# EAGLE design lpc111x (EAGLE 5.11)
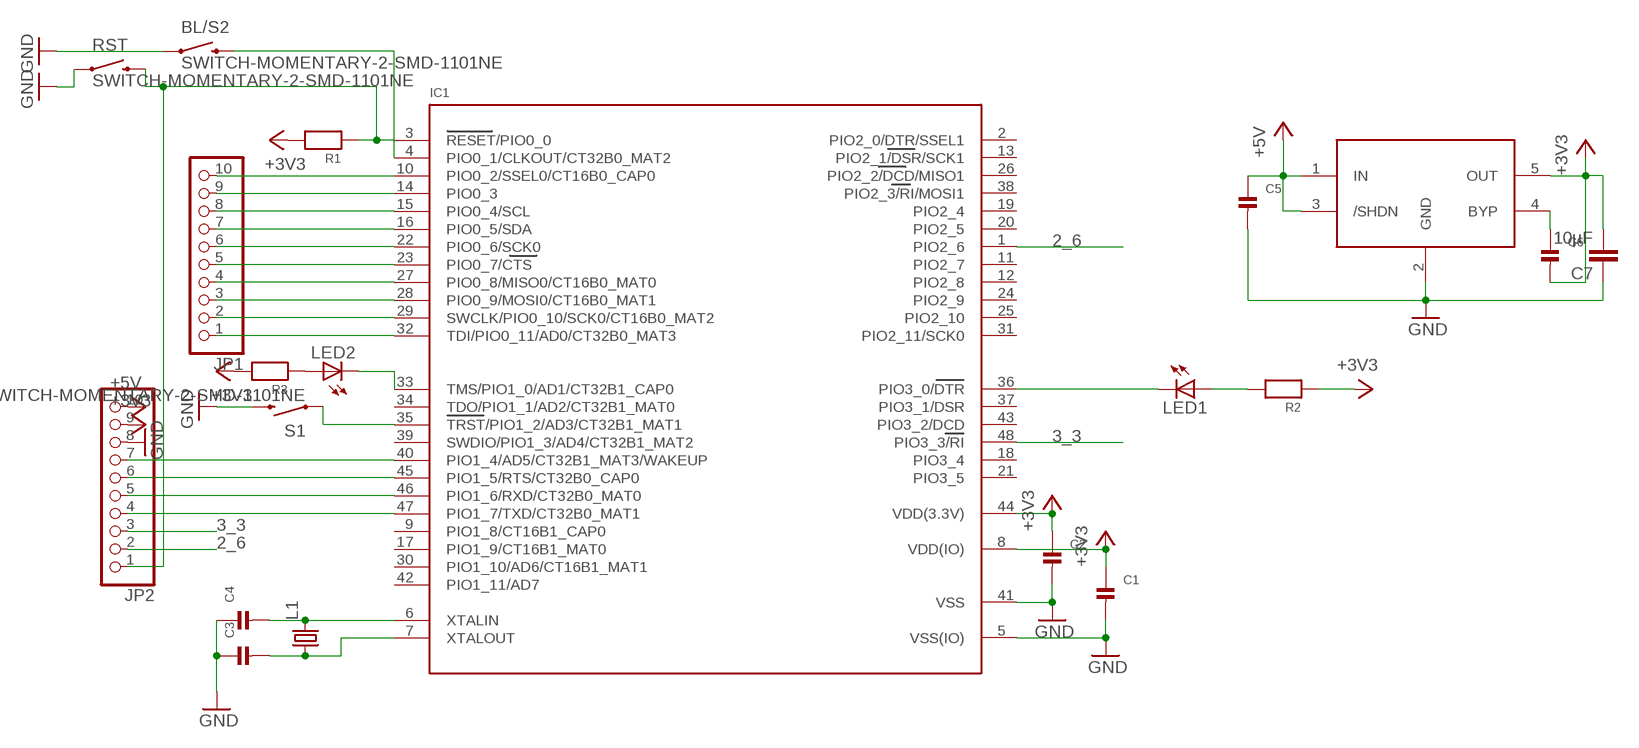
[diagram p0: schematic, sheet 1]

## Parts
BL/S2  SWITCH-MOMENTARY-2-SMD-1101NE  [TACTILE-SWITCH-1101NE]
C1  CAP_CERAMIC0603MINI  [0603-MINI]
C2  CAP_CERAMIC0603MINI  [0603-MINI]
C3  CAP_CERAMIC0603MINI  [0603-MINI]
C4  CAP_CERAMIC0603MINI  [0603-MINI]
C5  CAP_CERAMIC0603MINI  [0603-MINI]
C6  CAP_CERAMIC0603MINI  [0603-MINI]
C7  10µF  CAP0805  [0805]
IC1  LPC1113/4  [LQFP48]
IC2  LT1761  [SOT23-5L]
JP1  PINHD-1X10_2.54  [1X10]
JP2  PINHD-1X10_2.54  [1X10]
L1  X22-OSCILLATOR  [X22]
LED1  LEDCHIPLED_0805  [CHIPLED_0805]
LED2  LEDCHIPLED_0805  [CHIPLED_0805]
R1  RESISTOR0402  [0402]
R2  RESISTOR0402  [0402]
R3  RESISTOR0402  [0402]
RST  SWITCH-MOMENTARY-2-SMD-1101NE  [TACTILE-SWITCH-1101NE]
S1  SWITCH-MOMENTARY-2-SMD-1101NE  [TACTILE-SWITCH-1101NE]

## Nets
2_6: IC1.1(PIO2_6) JP2.2
3_3: IC1.48(PIO3_3/RI) JP2.3
+3V3: C1.1 C2.1 C6.2 C7.2 IC1.8(VDD(IO)) IC1.44(VDD(3.3V)) IC2.5(OUT) JP2.9 R1.2 R2.1 R3.2
+5V: C5.1 IC2.1(IN) IC2.3(/SHDN) JP2.10
GND: BL/S2.P$1 C1.2 C2.2 C3.1 C4.1 C5.2 C7.1 IC1.5(VSS(IO)) IC1.41(VSS) IC2.2(GND) JP2.8 RST.P$1 S1.P$2
N$1: IC1.32(TDI/PIO0_11/AD0/CT32B0_MAT3) JP1.1
N$2: IC1.29(SWCLK/PIO0_10/SCK0/CT16B0_MAT2) JP1.2
N$3: C3.2 IC1.7(XTALOUT) L1.1
N$4: C4.2 IC1.6(XTALIN) L1.3
N$5: IC1.28(PIO0_9/MOSI0/CT16B0_MAT1) JP1.3
N$6: IC1.27(PIO0_8/MISO0/CT16B0_MAT0) JP1.4
N$7: IC1.3(RESET/PIO0_0) JP2.1 R1.1 RST.P$2
N$8: IC1.23(PIO0_7/CTS) JP1.5
N$9: IC1.22(PIO0_6/SCK0) JP1.6
N$12: IC1.14(PIO0_3) JP1.9
N$13: IC1.10(PIO0_2/SSEL0/CT16B0_CAP0) JP1.10
N$16: IC1.45(PIO1_5/RTS/CT32B0_CAP0) JP2.6
N$17: IC1.40(PIO1_4/AD5/CT32B1_MAT3/WAKEUP) JP2.7
N$18: LED1.A R2.2
N$19: IC1.36(PIO3_0/DTR) LED1.C
N$20: IC1.35(TRST/PIO1_2/AD3/CT32B1_MAT1) S1.P$1
N$21: BL/S2.P$2 IC1.4(PIO0_1/CLKOUT/CT32B0_MAT2)
N$22: LED2.A R3.1
N$23: IC1.33(TMS/PIO1_0/AD1/CT32B1_CAP0) LED2.C
N$43: C6.1 IC2.4(BYP)
RX: IC1.46(PIO1_6/RXD/CT32B0_MAT0) JP2.5
SCL: IC1.15(PIO0_4/SCL) JP1.8
SDA: IC1.16(PIO0_5/SDA) JP1.7
TX: IC1.47(PIO1_7/TXD/CT32B0_MAT1) JP2.4
Unconnected: IC1.2(PIO2_0/DTR/SSEL1) IC1.9(PIO1_8/CT16B1_CAP0) IC1.11(PIO2_7) IC1.12(PIO2_8) IC1.13(PIO2_1/DSR/SCK1) IC1.17(PIO1_9/CT16B1_MAT0) IC1.18(PIO3_4) IC1.19(PIO2_4) IC1.20(PIO2_5) IC1.21(PIO3_5) IC1.24(PIO2_9) IC1.25(PIO2_10) IC1.26(PIO2_2/DCD/MISO1) IC1.30(PIO1_10/AD6/CT16B1_MAT1) IC1.31(PIO2_11/SCK0) IC1.34(TDO/PIO1_1/AD2/CT32B1_MAT0) IC1.37(PIO3_1/DSR) IC1.38(PIO2_3/RI/MOSI1) IC1.39(SWDIO/PIO1_3/AD4/CT32B1_MAT2) IC1.42(PIO1_11/AD7) IC1.43(PIO3_2/DCD)

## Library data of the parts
BL/S2 RST S1 = SparkFun:SWITCH-MOMENTARY-2
C1-C6 = microbuilder:CAP_CERAMIC: Ceramic Capacitors
C7 = SparkFun:CAP: Capacitor
IC1 = microbuilder:LPC1113/4: LPC1113/4 MCU QFP48 Package ARM Cortex M0, 50MHz Operation, 8 Channel 10-Bit ADC, 1²C, 2xSPI, UART, 2x16 Bit and 2x32 Bit Timers, Internal 12MHz Oscillator, 1.8-3.6V operation. Model Flash SRAM Part N°: Digikey Mouser LPC1113 24KB 8KB LPC1113FBD48/301 TBD TBD LPC1114 32KB 8KB LPC1114FBD48/301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; DIGIKEY#: 568-4950-ND; MANF: NXP; MANF#: LPC1114FBD48/301,1
IC2 = seb:LT1761
JP1 JP2 = pinhead-2:PINHD-1X10: PIN HEADER
L1 = seb:X22-OSCILLATOR
LED1 LED2 = led:LED: LED
R1-R3 = microbuilder:RESISTOR: Resistors

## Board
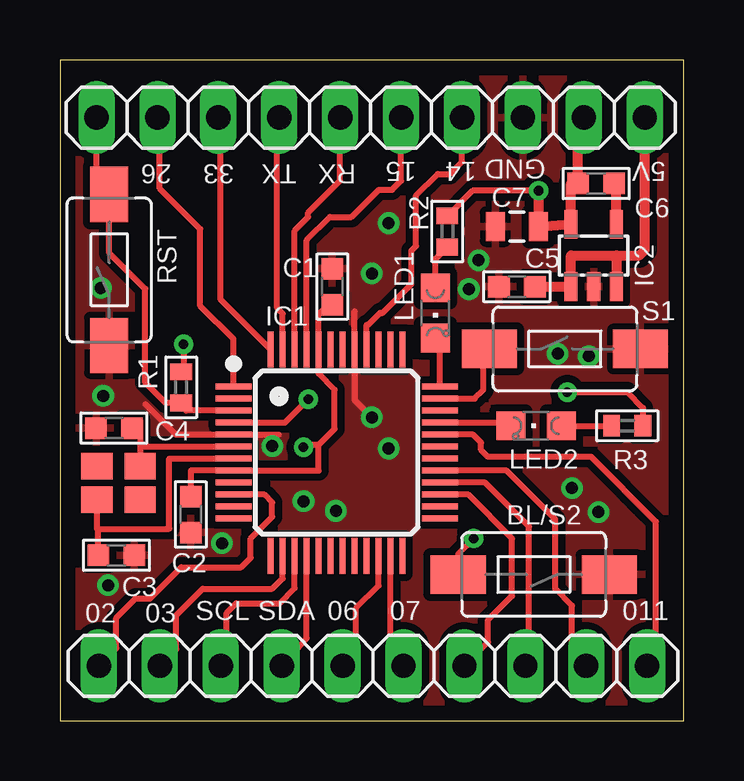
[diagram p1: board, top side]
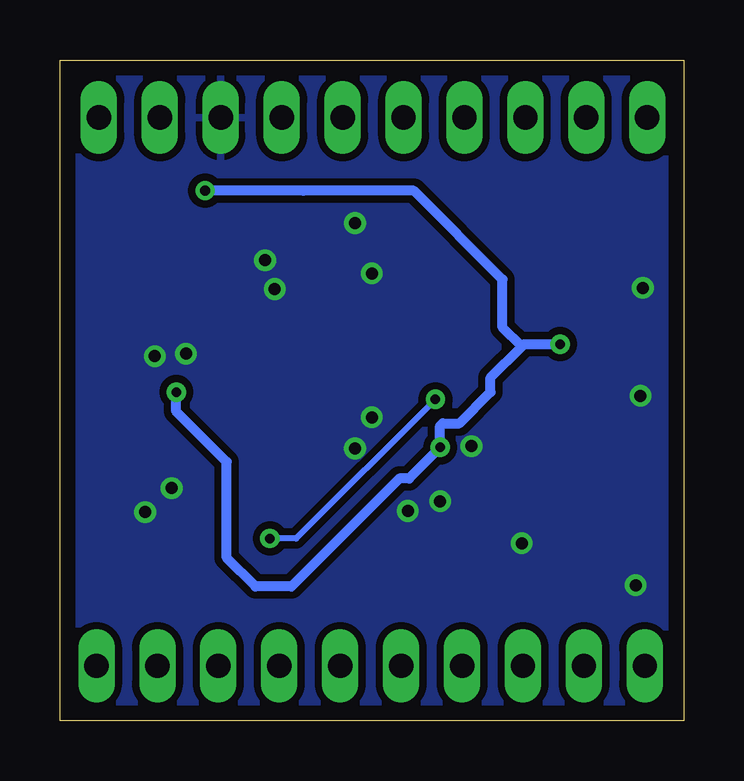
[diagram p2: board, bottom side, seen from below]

Size 26 x 27.55 mm. Coordinates in mm from the lower left corner, seen from the top.
Outline: 0,0 26,0 26,27.55 0,27.55 0,0
Copper layers (1*16): Top 0.035mm / dielectric 1.5mm / Bottom 0.035mm
Design rules "default *": minimum track width 10mil, minimum drill 24mil, track to track 8mil, track to pad 8mil, pad to pad 8mil, via to via 8mil, smd to smd 8mil, copper to edge 25mil, drill to drill 8mil, minimum pad ring 10mil, minimum via ring 8mil, stop-mask expansion 4mil, vias tented up to drill 40mil, thermal gap 10mil

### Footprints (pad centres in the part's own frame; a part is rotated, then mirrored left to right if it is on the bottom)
TACTILE-SWITCH-1101NE = smd 2.3 x 1.6: P$1 -3.15,0; P$2 3.15,0
0603-MINI = smd 0.9 x 0.9: 1 -0.75,0; 2 0.75,0
0805 = smd 0.8 x 1.2: 1 -0.9,0; 2 0.9,0
LQFP48 = smd 1.5 x 0.25: 1 -4.3,2.75; 2 -4.3,2.25; 3 -4.3,1.75; 4 -4.3,1.25; 5 -4.3,0.75; 6 -4.3,0.25; 7 -4.3,-0.25; 8 -4.3,-0.75; 9 -4.3,-1.25; 10 -4.3,-1.75; 11 -4.3,-2.25; 12 -4.3,-2.75; 25 4.3,-2.75; 26 4.3,-2.25; 27 4.3,-1.75; 28 4.3,-1.25; 29 4.3,-0.75; 30 4.3,-0.25; 31 4.3,0.25; 32 4.3,0.75; 33 4.3,1.25; 34 4.3,1.75; 35 4.3,2.25; 36 4.3,2.75 | smd 0.25 x 1.5: 13 -2.75,-4.3; 14 -2.25,-4.3; 15 -1.75,-4.3; 16 -1.25,-4.3; 17 -0.75,-4.3; 18 -0.25,-4.3; 19 0.25,-4.3; 20 0.75,-4.3; 21 1.25,-4.3; 22 1.75,-4.3; 23 2.25,-4.3; 24 2.75,-4.3; 37 2.75,4.3; 38 2.25,4.3; 39 1.75,4.3; 40 1.25,4.3; 41 0.75,4.3; 42 0.25,4.3; 43 -0.25,4.3; 44 -0.75,4.3; 45 -1.25,4.3; 46 -1.75,4.3; 47 -2.25,4.3; 48 -2.75,4.3
SOT23-5L = smd 0.55 x 1.2: 1 -0.95,-1.3; 2 0,-1.3; 3 0.95,-1.3; 4 0.95,1.3; 5 -0.95,1.3
1X10 = drill 1.016 long: 1 -11.43,0; 2 -8.89,0; 3 -6.35,0; 4 -3.81,0; 5 -1.27,0; 6 1.27,0; 7 3.81,0; 8 6.35,0; 9 8.89,0; 10 11.43,0
X22 = smd 1.3 x 1.1: 1 0.9,0.7; 2 -0.9,0.7; 3 -0.9,-0.7; 4 0.9,-0.7
CHIPLED_0805 = smd 1.2 x 1.2: A 0,-1.05; C 0,1.05
0402 = smd 0.7 x 0.9: 1 -0.65,0; 2 0.65,0

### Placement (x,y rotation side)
BL/S2  19.75,6.1 180 top
C1  11.35,18.1 90 top
C2  5.45,8.6 270 top
C3  2.35,6.9 180 top
C4  2.25,12.2 0 top
C5  19.05,18.1 180 top
C6  22.35,22.4 180 top
C7  19.05,20.6 0 top
IC1  11.53,11.18 0 top
IC2  22.25,19.4 0 top
JP1  13.05,2.29 180 top
JP2  12.95,25.15 0 top
L1  2.44,9.91 180 top
LED1  15.65,17 180 top
LED2  19.85,12.3 90 top
R1  5.05,13.9 90 top
R2  16.15,20.4 270 top
R3  23.65,12.3 0 top
RST  2.05,18.8 90 top
S1  21.05,15.5 0 top

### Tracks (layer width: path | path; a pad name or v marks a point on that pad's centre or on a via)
2_6
  Top 0.254: IC1.1 7.23,15.92 5.85,17.3 5.85,20.5 4.16,22.19 4.16,25.05 JP2.2
3_3
  Top 0.254: IC1.48 6.7,17.56 6.7,25.05 JP2.3
+3V3  (via drill 0.4)
  Top 0.254: C2.1 5.45,10.43 IC1.8 10.78,10.43 10.78,11.5 | C1.1 11.2,17.35 10.78,16.93 IC1.44 10.78,14.47 11.45,13.8 11.45,12.17 10.78,11.5 | v10.15,11.4 10.25,11.5 10.78,11.5 | R1.2 5.15,14.55 v5.15,15.7 | R2.1 17.2,22.1 v19.95,22.1 | R3.2 24.3,13.05 23.65,13.7 v21.15,13.7
  Top 0.406: v19.95,22.1 C7.2 IC2.5 21.3,22.4 C6.2 21.6,24.91 JP2.9
  Bottom 0.406: v19.95,22.1 15.85,22.1 11.25,22.1 7.55,18.4 7.55,16.4 6.75,15.6 | 6.75,15.6 8.05,14.3 8.05,13.7 9.35,12.4 10.05,12.4 10.15,12.3 v10.15,11.4 11.45,10.1 11.85,10.1 16.35,5.6 17.85,5.6 19.05,6.8 19.05,10.8 21.15,12.9 v21.15,13.7 | 6.75,15.6 6.65,15.7 v5.15,15.7
+5V
  Top 0.406: C5.1 IC2.1 21.3,19.4 23.2,19.4 | 23.2,19.4 IC2.3 | JP2.10 24.38,19.63 24.15,19.4 23.2,19.4
GND  (via drill 0.5)
  Top 0.254: IC1.41 12.28,14.97 | 12.28,14.97 12.28,13.37 v13,12.65 | 3.55,13.2 4.82,11.93 IC1.5 9.13,11.93 | 12.28,14.97 12.28,17.08
  other vias: 10.15,9.15 2,5.65 6.75,7.4 22.45,8.7 21.35,9.7 22.05,15.2 20.75,15.3 17.45,19.2 17.05,18 1.7,18.05 1.8,13.55 13,18.65 13.7,20.75 8.85,11.45 13.7,11.35 11.5,8.75
  pour Top (isolate 0.305): 0,0.4 26,0.4 26,27.15 0,27.15
  pour Bottom (isolate 0.305): 0,0.4 26,0.4 26,27.15 0,27.15
N$1
  Top 0.254: JP1.1 24.85,3.26 24.85,8.3 22.15,11 17.85,11 17.55,11.3 17.55,11.6 17.22,11.93 IC1.32
N$2
  Top 0.254: IC1.29 18.62,10.43 20.65,8.4 20.65,5.5 21.35,4.8 21.35,2.99 JP1.2
N$3
  Top 0.254: IC1.7 4.55,10.93 4.55,8 1.6,8 | L1.1 1.54,8 1.6,8 | C3.2 1.6,8
N$4
  Top 0.254: 3.34,11.43 IC1.6 | 3.34,11.43 L1.3 | C4.2 3.34,12.5 3.34,11.43
N$5
  Top 0.254: IC1.28 17.72,9.93 19.55,8.1 19.55,2.25 JP1.3
N$6
  Top 0.254: IC1.27 17.02,9.43 18.85,7.6 18.85,5.2 17.85,4.2 17.85,3.28 JP1.4
N$7
  Top 0.254: IC1.3 5.27,12.93 R1.1 4.4,13.25 3.55,14.1 3.55,18 2.05,19.5 RST.P$2 1.52,21.88 JP2.1
N$8
  Top 0.254: IC1.23 13.78,2.94 JP1.5
N$9
  Top 0.254: IC1.22 13.28,5.63 12.35,4.7 12.35,2.97 JP1.6
N$12
  Top 0.254: IC1.14 9.28,5.93 8.85,5.5 5.95,5.5 4.85,4.4 4.85,2.98 JP1.9
N$13
  Top 0.254: IC1.10 8.52,9.43 8.85,9.1 8.85,8.5 7.95,7.6 7.95,6.8 7.55,6.4 5.05,6.4 3.75,5.1 3.15,5.1 2.35,4.3 2.35,3.02 JP1.10
N$16
  Top 0.254: IC1.45 10.28,20.03 11.25,21 12.15,21 13.29,22.14 13.85,22.14 14.22,22.51 JP2.6
N$17
  Top 0.254: IC1.40 12.78,16.5 12.85,16.5 13.35,17 13.45,17 14.65,18.2 14.65,19.6 14.85,19.8 14.85,21.9 15.75,22.8 16.25,22.8 16.76,23.31 JP2.7
N$18
  Top 0.254: R2.2 15.65,19.25 LED1.A
N$19
  Top 0.254: LED1.C 15.83,15.63 IC1.36
N$20
  Top 0.254: IC1.35 17.28,13.43 17.65,13.8 17.65,14.85 S1.P$1
N$21  (via drill 0.4)
  Top 0.254: BL/S2.P$2 16.6,6.95 v17.25,7.6 | IC1.4 8.78,12.43 9.38,12.43 v10.35,13.4
  Bottom 0.254: v17.25,7.6 16.15,7.6 v10.35,13.4
N$22
  Top 0.254: LED2.A R3.1
N$23
  Top 0.254: IC1.33 18.67,12.43 LED2.C
N$43
  Top 0.406: C6.1 23.2,22.4 IC2.4
RX
  Top 0.254: IC1.46 9.78,20.43 10.35,21 10.35,21.18 11.68,22.51 JP2.5
SCL
  Top 0.254: IC1.15 9.78,5.53 9.15,4.9 7.35,4.9 6.95,4.5 6.95,2.65 JP1.8
SDA
  Top 0.254: IC1.16 10.28,3.44 JP1.7
TX
  Top 0.254: IC1.47 9.28,16.97 9.05,17.2 9.05,25.06 JP2.4

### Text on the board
tNames: 26 | 33 | TX | RX | 15 | 14 | GND | 5V | 02 | 03 | SCL | SDA | 06 | 07 | 011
